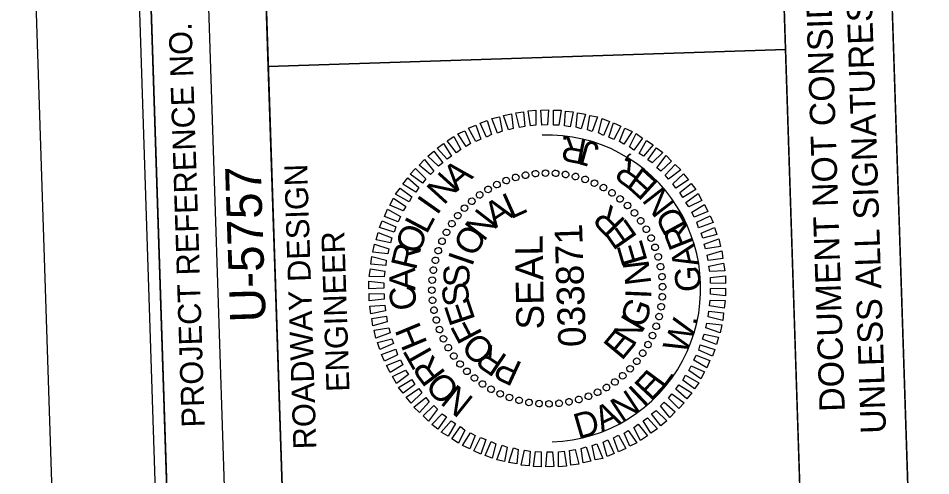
# Model space of a CAD drawing. Extents: x 1627314 to 1628469, y 762309 to 764247.
# Drawn here: x 1627314.2 to 1627512.6, y 763788.2 to 763887.6 of the extents above; entities that cross this region are included whole.
import ezdxf

# ---------------------------------------------------------------- set-up
doc = ezdxf.new("R2010")
doc.units = 0
for name, color, linetype in [('Old_Level_2', 7, 'Continuous'), ('Scratch_Level_0', 7, 'Continuous'), ('Sheet Data Field CELL', 7, 'Continuous'), ('Sheet Plot Border Inside CELL', 7, 'Continuous'), ('Sheet Plot Border Outside CELL', 7, 'Continuous'), ('Sheet Professional Seal CELL', 7, 'Continuous'), ('Sheet Profile CELL', 7, 'Continuous'), ('Sheet Profile Grid Major CELL', 7, 'Continuous'), ('Sheet Profile Grid Minor CELL', 7, 'Continuous'), ('Sheet Sticker Exception Certification CELL', 7, 'Continuous')]:
    doc.layers.add(name, color=color, linetype=linetype)

msp = doc.modelspace()

# ---------------------------------------------------------------- linework, layer by layer
at = {"layer": 'Old_Level_2'}
msp.add_lwpolyline([(1627507.79, 763781.61), (1627501.25, 763981.49), (1627565.16, 763983.58), (1627571.7, 763783.7)], close=True, dxfattribs=at)
at = {"layer": 'Scratch_Level_0'}
msp.add_arc((1627429.24, 763828.9), 33.36, 271.8735, 91.8735, dxfattribs=at)
at = {"layer": 'Sheet Plot Border Inside CELL'}
msp.add_lwpolyline([(1628446.34, 762357.53), (1628391.86, 764023.14), (1627337.33, 763988.65), (1627391.81, 762323.04)], close=True, dxfattribs=at)
at = {"layer": 'Sheet Plot Border Outside CELL'}
msp.add_lwpolyline([(1628469.21, 762345.27), (1628413.63, 764044.37), (1627314.22, 764008.4), (1627369.79, 762309.31)], close=True, dxfattribs=at)
at = {"layer": 'Sheet Professional Seal CELL'}
for p, q in [((1627420.27, 763852.37), (1627420.27, 763852.37)), ((1627422.35, 763853.03), (1627422.35, 763853.03)), ((1627424.53, 763853.51), (1627424.53, 763853.51)), ((1627426.67, 763853.88), (1627426.67, 763853.88)), ((1627428.87, 763854), (1627428.87, 763854)), ((1627431.07, 763853.92), (1627431.07, 763853.92)), ((1627433.23, 763853.64), (1627433.23, 763853.64)), ((1627435.35, 763853.26), (1627435.35, 763853.26)), ((1627437.47, 763852.63), (1627437.47, 763852.63)), ((1627416.38, 763850.44), (1627416.38, 763850.44)), ((1627418.3, 763851.5), (1627418.3, 763851.5)), ((1627439.5, 763851.79), (1627439.5, 763851.79)), ((1627441.48, 763850.86), (1627441.48, 763850.86)), ((1627414.52, 763849.23), (1627414.52, 763849.23)), ((1627443.32, 763849.67), (1627443.32, 763849.67)), ((1627445.11, 763848.38), (1627445.11, 763848.38)), ((1627411.21, 763846.37), (1627411.21, 763846.37)), ((1627412.81, 763847.92), (1627412.81, 763847.92)), ((1627446.71, 763846.93), (1627446.71, 763846.93)), ((1627409.76, 763844.77), (1627409.76, 763844.77)), ((1627448.26, 763845.33), (1627448.26, 763845.33)), ((1627408.47, 763842.98), (1627408.47, 763842.98)), ((1627449.57, 763843.62), (1627449.57, 763843.62)), ((1627407.28, 763841.14), (1627407.28, 763841.14)), ((1627450.78, 763841.76), (1627450.78, 763841.76)), ((1627406.34, 763839.15), (1627406.34, 763839.15)), ((1627451.84, 763839.84), (1627451.84, 763839.84)), ((1627405.51, 763837.13), (1627405.51, 763837.13)), ((1627452.71, 763837.87), (1627452.71, 763837.87)), ((1627404.88, 763835), (1627404.88, 763835)), ((1627453.38, 763835.79), (1627453.38, 763835.79)), ((1627404.5, 763832.89), (1627404.5, 763832.89)), ((1627453.85, 763833.6), (1627453.85, 763833.6)), ((1627404.22, 763830.73), (1627404.22, 763830.73)), ((1627454.22, 763831.46), (1627454.22, 763831.46)), ((1627404.14, 763828.53), (1627404.14, 763828.53)), ((1627429.24, 763828.9), (1627429.24, 763828.9)), ((1627454.34, 763829.27), (1627454.34, 763829.27)), ((1627454.26, 763827.06), (1627454.26, 763827.06)), ((1627404.26, 763826.33), (1627404.26, 763826.33)), ((1627453.98, 763824.9), (1627453.98, 763824.9)), ((1627404.63, 763824.19), (1627404.63, 763824.19)), ((1627453.6, 763822.79), (1627453.6, 763822.79)), ((1627405.1, 763822), (1627405.1, 763822)), ((1627452.97, 763820.67), (1627452.97, 763820.67)), ((1627405.77, 763819.92), (1627405.77, 763819.92)), ((1627452.14, 763818.64), (1627452.14, 763818.64)), ((1627406.64, 763817.95), (1627406.64, 763817.95)), ((1627451.2, 763816.66), (1627451.2, 763816.66)), ((1627407.7, 763816.04), (1627407.7, 763816.04)), ((1627450.01, 763814.82), (1627450.01, 763814.82)), ((1627408.91, 763814.17), (1627408.91, 763814.17)), ((1627448.72, 763813.03), (1627448.72, 763813.03)), ((1627410.22, 763812.47), (1627410.22, 763812.47)), ((1627411.77, 763810.87), (1627411.77, 763810.87)), ((1627447.27, 763811.43), (1627447.27, 763811.43)), ((1627413.37, 763809.42), (1627413.37, 763809.42)), ((1627443.96, 763808.57), (1627443.96, 763808.57)), ((1627445.67, 763809.87), (1627445.67, 763809.87)), ((1627415.16, 763808.13), (1627415.16, 763808.13)), ((1627417, 763806.94), (1627417, 763806.94)), ((1627442.1, 763807.36), (1627442.1, 763807.36)), ((1627418.98, 763806), (1627418.98, 763806)), ((1627421.01, 763805.17), (1627421.01, 763805.17)), ((1627436.13, 763804.76), (1627436.13, 763804.76)), ((1627438.21, 763805.43), (1627438.21, 763805.43)), ((1627440.19, 763806.29), (1627440.19, 763806.29)), ((1627423.13, 763804.53), (1627423.13, 763804.53)), ((1627425.25, 763804.15), (1627425.25, 763804.15)), ((1627427.41, 763803.87), (1627427.41, 763803.87)), ((1627429.61, 763803.8), (1627429.61, 763803.8)), ((1627431.81, 763803.92), (1627431.81, 763803.92)), ((1627433.95, 763804.29), (1627433.95, 763804.29))]:
    msp.add_line(p, q, dxfattribs=at)
for points in [[(1627418.43, 763862.66), (1627417.18, 763865.82), (1627418.82, 763866.18), (1627419.47, 763863.05)], [(1627420.81, 763863.34), (1627419.76, 763866.46), (1627421.45, 763866.81), (1627421.85, 763863.67)], [(1627423.19, 763863.87), (1627422.39, 763867.09), (1627424.08, 763867.3), (1627424.39, 763864.11)], [(1627425.58, 763864.25), (1627425.08, 763867.48), (1627426.77, 763867.64), (1627426.78, 763864.39)], [(1627428.08, 763864.38), (1627427.82, 763867.62), (1627429.52, 763867.68), (1627429.28, 763864.42)], [(1627430.58, 763864.41), (1627430.57, 763867.66), (1627432.23, 763867.62), (1627431.78, 763864.35)], [(1627432.99, 763864.24), (1627433.18, 763867.45), (1627434.89, 763867.3), (1627434.19, 763864.03)], [(1627435.55, 763863.92), (1627435.85, 763867.03), (1627437.56, 763866.74), (1627436.61, 763863.56)], [(1627437.97, 763863.35), (1627438.52, 763866.47), (1627440.18, 763866.17), (1627439.03, 763862.99)], [(1627413.74, 763860.81), (1627412.14, 763863.71), (1627413.72, 763864.41), (1627414.82, 763861.34)], [(1627416.06, 763861.78), (1627414.66, 763864.79), (1627416.19, 763865.39), (1627417.09, 763862.32)], [(1627440.39, 763862.68), (1627441.19, 763865.81), (1627442.76, 763865.21), (1627441.46, 763862.16)], [(1627442.62, 763861.75), (1627443.67, 763864.89), (1627445.25, 763864.19), (1627443.74, 763861.29)], [(1627411.62, 763859.74), (1627409.78, 763862.48), (1627411.31, 763863.18), (1627412.55, 763860.37)], [(1627444.95, 763860.83), (1627446.11, 763863.72), (1627447.68, 763863.02), (1627445.92, 763860.26)], [(1627447.14, 763859.7), (1627448.55, 763862.55), (1627449.98, 763861.59), (1627448.07, 763858.93)], [(1627407.46, 763857), (1627405.28, 763859.38), (1627406.7, 763860.38), (1627408.39, 763857.63)], [(1627409.47, 763858.37), (1627407.48, 763860.95), (1627408.95, 763861.95), (1627410.44, 763859.1)], [(1627449.19, 763858.26), (1627450.8, 763861.02), (1627452.28, 763860.12), (1627450.16, 763857.65)], [(1627405.56, 763855.44), (1627403.24, 763857.66), (1627404.55, 763858.76), (1627406.54, 763856.17)], [(1627451.14, 763856.83), (1627453, 763859.49), (1627454.34, 763858.43), (1627452.06, 763856.16)], [(1627403.82, 763853.63), (1627401.4, 763855.7), (1627402.56, 763856.94), (1627404.59, 763854.4)], [(1627453.1, 763855.14), (1627455.06, 763857.76), (1627456.25, 763856.54), (1627453.92, 763854.37)], [(1627402.13, 763851.77), (1627399.46, 763853.74), (1627400.62, 763854.98), (1627402.85, 763852.75)], [(1627454.9, 763853.55), (1627457.02, 763855.82), (1627458.26, 763854.66), (1627455.63, 763852.62)], [(1627400.64, 763849.82), (1627397.83, 763851.58), (1627398.89, 763852.92), (1627401.31, 763850.8)], [(1627456.51, 763851.6), (1627458.84, 763853.83), (1627459.93, 763852.51), (1627457.19, 763850.67)], [(1627399.21, 763847.73), (1627396.25, 763849.38), (1627397.26, 763850.71), (1627399.77, 763848.84)], [(1627458.07, 763849.75), (1627460.56, 763851.68), (1627461.55, 763850.41), (1627458.71, 763848.67)], [(1627397.92, 763845.73), (1627395.03, 763846.99), (1627395.83, 763848.52), (1627398.49, 763846.7)], [(1627459.4, 763847.59), (1627462.03, 763849.53), (1627462.88, 763848.01), (1627460.03, 763846.66)], [(1627460.66, 763845.48), (1627463.41, 763847.17), (1627464.16, 763845.65), (1627461.15, 763844.4)], [(1627396.85, 763843.4), (1627393.86, 763844.55), (1627394.51, 763846.12), (1627397.36, 763844.51)], [(1627461.79, 763843.32), (1627464.64, 763844.71), (1627465.29, 763843.23), (1627462.13, 763842.08)], [(1627395.97, 763841.12), (1627392.79, 763842.16), (1627393.34, 763843.58), (1627396.29, 763842.28)], [(1627395.15, 763838.84), (1627392.02, 763839.49), (1627392.47, 763841.05), (1627395.46, 763839.9)], [(1627462.67, 763840.9), (1627465.63, 763842.14), (1627466.13, 763840.61), (1627463.05, 763839.86)], [(1627394.58, 763836.42), (1627391.31, 763836.81), (1627391.66, 763838.52), (1627394.79, 763837.48)], [(1627463.39, 763838.52), (1627466.51, 763839.67), (1627466.91, 763837.98), (1627463.68, 763837.48)], [(1627464.02, 763836.14), (1627467.19, 763837.04), (1627467.4, 763835.4), (1627464.21, 763834.94)], [(1627394.11, 763833.85), (1627390.9, 763834.2), (1627391.09, 763835.85), (1627394.22, 763835.06)], [(1627464.4, 763833.75), (1627467.58, 763834.4), (1627467.84, 763832.71), (1627464.59, 763832.55)], [(1627393.79, 763831.44), (1627390.53, 763831.53), (1627390.78, 763833.19), (1627393.95, 763832.65)], [(1627393.72, 763828.94), (1627390.47, 763828.83), (1627390.47, 763830.48), (1627393.73, 763830.14)], [(1627464.73, 763831.26), (1627467.97, 763831.61), (1627467.98, 763829.96), (1627464.72, 763830.06)], [(1627464.76, 763828.86), (1627468.01, 763828.96), (1627468.01, 763827.31), (1627464.75, 763827.66)], [(1627393.75, 763826.54), (1627390.51, 763826.18), (1627390.5, 763827.83), (1627393.76, 763827.74)], [(1627394.08, 763824.04), (1627390.9, 763823.39), (1627390.64, 763825.08), (1627393.89, 763825.24)], [(1627464.69, 763826.35), (1627467.95, 763826.26), (1627467.7, 763824.6), (1627464.53, 763825.15)], [(1627394.46, 763821.66), (1627391.29, 763820.75), (1627391.08, 763822.4), (1627394.27, 763822.85)], [(1627464.37, 763823.94), (1627467.58, 763823.6), (1627467.39, 763821.94), (1627464.26, 763822.74)], [(1627463.9, 763821.38), (1627467.17, 763820.98), (1627466.83, 763819.27), (1627463.69, 763820.32)], [(1627395.09, 763819.28), (1627391.97, 763818.12), (1627391.57, 763819.81), (1627394.8, 763820.32)], [(1627463.33, 763818.96), (1627466.46, 763818.31), (1627466.01, 763816.74), (1627463.02, 763817.9)], [(1627395.81, 763816.9), (1627392.85, 763815.65), (1627392.35, 763817.18), (1627395.43, 763817.94)], [(1627462.51, 763816.68), (1627465.69, 763815.63), (1627465.14, 763814.21), (1627462.2, 763815.52)], [(1627396.69, 763814.48), (1627393.84, 763813.08), (1627393.19, 763814.56), (1627396.35, 763815.71)], [(1627397.82, 763812.31), (1627395.07, 763810.62), (1627394.32, 763812.15), (1627397.33, 763813.4)], [(1627461.63, 763814.4), (1627464.62, 763813.25), (1627463.97, 763811.67), (1627461.12, 763813.28)], [(1627399.09, 763810.2), (1627396.45, 763808.26), (1627395.6, 763809.79), (1627398.45, 763811.13)], [(1627460.56, 763812.06), (1627463.45, 763810.81), (1627462.65, 763809.28), (1627459.99, 763811.09)], [(1627400.41, 763808.04), (1627397.92, 763806.11), (1627396.93, 763807.38), (1627399.77, 763809.12)], [(1627459.27, 763810.07), (1627462.23, 763808.41), (1627461.22, 763807.08), (1627458.71, 763808.95)], [(1627401.97, 763806.19), (1627399.64, 763803.97), (1627398.55, 763805.28), (1627401.29, 763807.12)], [(1627457.84, 763807.97), (1627460.65, 763806.21), (1627459.59, 763804.88), (1627457.17, 763807)], [(1627403.58, 763804.24), (1627401.46, 763801.97), (1627400.22, 763803.13), (1627402.85, 763805.17)], [(1627456.35, 763806.02), (1627459.02, 763804.06), (1627457.86, 763802.82), (1627455.63, 763805.05)], [(1627405.39, 763802.65), (1627403.42, 763800.04), (1627402.23, 763801.25), (1627404.56, 763803.43)], [(1627454.66, 763804.16), (1627457.08, 763802.09), (1627455.92, 763800.85), (1627453.89, 763803.39)], [(1627407.34, 763800.97), (1627405.48, 763798.3), (1627404.14, 763799.36), (1627406.42, 763801.64)], [(1627451.02, 763800.79), (1627453.2, 763798.41), (1627451.78, 763797.42), (1627450.09, 763800.16)], [(1627452.92, 763802.36), (1627455.24, 763800.13), (1627453.93, 763799.04), (1627451.94, 763801.62)], [(1627409.29, 763799.53), (1627407.68, 763796.77), (1627406.2, 763797.68), (1627408.32, 763800.15)], [(1627411.34, 763798.1), (1627409.93, 763795.25), (1627408.5, 763796.2), (1627410.41, 763798.87)], [(1627449.01, 763799.43), (1627451, 763796.84), (1627449.53, 763795.84), (1627448.04, 763798.7)], [(1627413.53, 763796.97), (1627412.37, 763794.08), (1627410.8, 763794.78), (1627412.56, 763797.53)], [(1627444.74, 763796.99), (1627446.34, 763794.09), (1627444.76, 763793.39), (1627443.66, 763796.45)], [(1627446.86, 763798.06), (1627448.7, 763795.32), (1627447.17, 763794.61), (1627445.93, 763797.43)], [(1627415.86, 763796.04), (1627414.81, 763792.91), (1627413.24, 763793.6), (1627414.74, 763796.51)], [(1627418.09, 763795.11), (1627417.29, 763791.99), (1627415.72, 763792.59), (1627417.02, 763795.63)], [(1627420.51, 763794.44), (1627419.96, 763791.32), (1627418.3, 763791.62), (1627419.45, 763794.81)], [(1627440.05, 763795.13), (1627441.3, 763791.97), (1627439.66, 763791.62), (1627439.01, 763794.75)], [(1627442.42, 763796.01), (1627443.82, 763793), (1627442.29, 763792.4), (1627441.39, 763795.48)], [(1627422.93, 763793.87), (1627422.63, 763790.76), (1627420.92, 763791.05), (1627421.87, 763794.24)], [(1627425.49, 763793.56), (1627425.3, 763790.35), (1627423.59, 763790.49), (1627424.29, 763793.77)], [(1627427.9, 763793.38), (1627427.91, 763790.13), (1627426.25, 763790.18), (1627426.7, 763793.44)], [(1627430.4, 763793.42), (1627430.66, 763790.17), (1627428.96, 763790.12), (1627429.2, 763793.38)], [(1627432.9, 763793.55), (1627433.4, 763790.31), (1627431.71, 763790.16), (1627431.7, 763793.41)], [(1627435.29, 763793.93), (1627436.09, 763790.7), (1627434.4, 763790.5), (1627434.09, 763793.69)], [(1627437.67, 763794.45), (1627438.72, 763791.34), (1627437.03, 763790.98), (1627436.63, 763794.12)]]:
    msp.add_lwpolyline(points, close=True, dxfattribs=at)
for centre, major_axis in [((1627424.51, 763853.53), (-0.136, 0.707)), ((1627426.67, 763853.85), (-0.074, 0.716)), ((1627428.86, 763853.97), (-0.011, 0.72)), ((1627431.05, 763853.91), (0.052, 0.718)), ((1627433.22, 763853.66), (0.114, 0.711)), ((1627418.3, 763851.46), (-0.314, 0.648)), ((1627420.3, 763852.33), (-0.257, 0.673)), ((1627422.38, 763853.02), (-0.197, 0.693)), ((1627435.36, 763853.22), (0.176, 0.698)), ((1627437.46, 763852.59), (0.236, 0.68)), ((1627439.49, 763851.79), (0.294, 0.657)), ((1627416.37, 763850.42), (-0.369, 0.618)), ((1627441.45, 763850.81), (0.35, 0.629)), ((1627443.31, 763849.66), (0.404, 0.596)), ((1627412.83, 763847.86), (-0.471, 0.544)), ((1627414.54, 763849.22), (-0.422, 0.583)), ((1627445.07, 763848.35), (0.454, 0.559)), ((1627411.24, 763846.36), (-0.517, 0.501)), ((1627446.7, 763846.9), (0.501, 0.517)), ((1627409.78, 763844.72), (-0.559, 0.454)), ((1627448.2, 763845.31), (0.544, 0.471)), ((1627449.56, 763843.59), (0.583, 0.422)), ((1627408.48, 763842.97), (-0.596, 0.404)), ((1627450.77, 763841.77), (0.618, 0.369)), ((1627407.33, 763841.1), (-0.629, 0.35)), ((1627451.81, 763839.84), (0.648, 0.314)), ((1627406.35, 763839.15), (-0.657, 0.294)), ((1627452.67, 763837.83), (0.673, 0.257)), ((1627405.54, 763837.11), (-0.68, 0.236)), ((1627453.36, 763835.76), (0.693, 0.197)), ((1627404.92, 763835.02), (-0.698, 0.176)), ((1627453.87, 763833.63), (0.707, 0.136)), ((1627404.48, 763832.88), (-0.711, 0.114)), ((1627404.23, 763830.7), (-0.718, 0.052)), ((1627454.19, 763831.46), (0.716, 0.074)), ((1627404.16, 763828.51), (-0.72, -0.011)), ((1627454.32, 763829.28), (0.72, 0.011)), ((1627404.29, 763826.33), (-0.716, -0.074)), ((1627454.26, 763827.09), (0.718, -0.052)), ((1627404.61, 763824.17), (-0.707, -0.136)), ((1627454, 763824.92), (0.711, -0.114)), ((1627405.12, 763822.04), (-0.693, -0.197)), ((1627453.56, 763822.78), (0.698, -0.176)), ((1627405.81, 763819.96), (-0.673, -0.257)), ((1627452.94, 763820.68), (0.68, -0.236)), ((1627406.67, 763817.95), (-0.648, -0.314)), ((1627452.13, 763818.65), (0.657, -0.294)), ((1627407.71, 763816.03), (-0.618, -0.369)), ((1627451.15, 763816.69), (0.629, -0.35)), ((1627408.92, 763814.2), (-0.583, -0.422)), ((1627450, 763814.83), (0.596, -0.404)), ((1627410.28, 763812.48), (-0.544, -0.471)), ((1627448.7, 763813.07), (0.559, -0.454)), ((1627411.78, 763810.89), (-0.501, -0.517)), ((1627445.65, 763809.93), (0.471, -0.544)), ((1627447.24, 763811.44), (0.517, -0.501)), ((1627413.41, 763809.44), (-0.454, -0.559)), ((1627415.17, 763808.14), (-0.404, -0.596)), ((1627443.94, 763808.57), (0.422, -0.583)), ((1627417.03, 763806.99), (-0.35, -0.629)), ((1627418.99, 763806.01), (-0.294, -0.657)), ((1627440.18, 763806.33), (0.314, -0.648)), ((1627442.11, 763807.37), (0.369, -0.618)), ((1627421.02, 763805.2), (-0.236, -0.68)), ((1627423.12, 763804.58), (-0.176, -0.698)), ((1627425.26, 763804.13), (-0.114, -0.711)), ((1627427.44, 763803.88), (-0.052, -0.718)), ((1627431.81, 763803.95), (0.074, -0.716)), ((1627433.97, 763804.27), (0.136, -0.707)), ((1627436.1, 763804.77), (0.197, -0.693)), ((1627438.18, 763805.46), (0.257, -0.673)), ((1627429.62, 763803.82), (0.011, -0.72))]:
    msp.add_ellipse(centre, major_axis=major_axis, ratio=0.999708, dxfattribs=at)
at = {"layer": 'Sheet Profile CELL'}
for p, q in [((1627359.37, 763776.71), (1627352.83, 763976.65)), ((1627368.59, 763877.11), (1627480.98, 763880.79))]:
    msp.add_line(p, q, dxfattribs=at)
for points in [[(1627340.28, 763976.24), (1627389.32, 762477.04), (1628438.76, 762511.37), (1628389.72, 764010.57)], [(1627368.59, 763877.11), (1627365.32, 763977.06), (1627477.76, 763980.74), (1627481.03, 763880.79)], [(1627346.82, 763776.3), (1627340.28, 763976.24), (1627365.32, 763977.06), (1627371.86, 763777.12)], [(1627371.86, 763777.12), (1627368.59, 763877.11), (1627481.03, 763880.79), (1627484.3, 763780.79)]]:
    msp.add_lwpolyline(points, close=True, dxfattribs=at)
at = {"layer": 'Sheet Profile Grid Major CELL'}
msp.add_lwpolyline([(1627363.17, 763276.61), (1627361.53, 763326.59), (1627861.27, 763342.93), (1627859.63, 763392.91), (1627359.9, 763376.56), (1627358.26, 763426.53), (1627858, 763442.88), (1627856.36, 763492.85), (1627356.63, 763476.51), (1627354.99, 763526.48), (1627854.73, 763542.83), (1627853.09, 763592.8), (1627353.36, 763576.45), (1627351.73, 763626.43), (1627851.46, 763642.77), (1627849.82, 763692.75), (1627350.09, 763676.4), (1627348.46, 763726.37), (1627848.19, 763742.72), (1627846.55, 763792.69), (1627346.82, 763776.35), (1627345.96, 763802.63)], dxfattribs=at)
at = {"layer": 'Sheet Sticker Exception Certification CELL'}
for p, q in [((1627501.25, 763981.49), (1627507.79, 763781.56)), ((1627501.25, 763981.49), (1627507.79, 763781.56)), ((1627484.3, 763780.79), (1627477.76, 763980.72)), ((1627484.3, 763780.79), (1627477.76, 763980.72))]:
    msp.add_line(p, q, dxfattribs=at)

# ---------------------------------------------------------------- texts
at = {"layer": 'Sheet Data Field CELL'}
msp.add_text('U-5757', height=7.75, rotation=91.8735, dxfattribs=at).set_placement((1627368.04, 763821.64))
at = {"layer": 'Sheet Professional Seal CELL'}
for s, height, rotation, p in [('A', 5.64, 40.4906, (1627409.59, 763849.87)), ('N', 5.64, 47.6924, (1627406.74, 763846.82)), ('I', 5.64, 54.8936, (1627405.26, 763844.62)), ('L', 5.64, 24.2743, (1627421.3, 763843.9)), ('A', 5.64, 33.6337, (1627417.91, 763841.83)), ('R', 5.64, 134.3549, (1627446.52, 763843.57)), ('L', 5.64, 62.0943, (1627403, 763840.5)), ('N', 5.64, 52.3501, (1627415.41, 763838.9)), ('O', 5.64, 69.2946, (1627401.29, 763836.04)), ('E', 5.64, 124.9976, (1627448.98, 763840.1)), ('O', 5.64, 61.707, (1627413.52, 763835.49)), ('R', 5.64, 76.4946, (1627400.65, 763832.66)), ('SEAL', 5.998, 90.8735, (1627428.53, 763820.02)), ('E', 5.64, 106.2852, (1627451.11, 763834.87)), ('I', 5.64, 71.0631, (1627412.88, 763833.46)), ('N', 5.64, 96.9299, (1627451.87, 763829.94)), ('A', 5.64, 90.8938, (1627400.59, 763828.46)), ('S', 5.64, 89.7739, (1627412.32, 763829.14)), ('C', 5.64, 98.0933, (1627401.02, 763824.52)), ('S', 5.64, 99.1291, (1627412.49, 763825.55)), ('E', 5.64, 108.4845, (1627413.65, 763822.13)), ('I', 5.64, 87.5747, (1627451.83, 763826.58)), ('G', 5.64, 68.8637, (1627450.14, 763819.98)), ('N', 5.64, 59.5074, (1627448.02, 763816.1)), ('H', 5.64, 112.4929, (1627403.27, 763816.99)), ('F', 5.64, 117.8405, (1627415.26, 763818.98)), ('O', 5.64, 136.5547, (1627418.31, 763815.78)), ('E', 5.64, 50.1504, (1627445.42, 763813.02)), ('R', 5.64, 145.9131, (1627420.82, 763814.11)), ('T', 5.64, 119.6932, (1627405.02, 763813.8)), ('R', 5.64, 126.894, (1627407.33, 763810.47)), ('P', 5.64, 155.2724, (1627424.07, 763812.62)), ('O', 5.64, 134.0952, (1627410.54, 763807.12)), ('N', 5.64, 141.297, (1627413.52, 763804.92))]:
    msp.add_text(s, height=height, rotation=rotation, dxfattribs=at).set_placement(p)
at = {"layer": 'Sheet Profile CELL'}
for s, height, p in [('PROJECT REFERENCE NO.', 5.0001, (1627354.78, 763798.78)), ('ROADWAY DESIGN', 5.0001, (1627379.05, 763794.02)), ('ENGINEER', 5, (1627386.24, 763806.51))]:
    msp.add_text(s, height=height, rotation=91.8735, dxfattribs=at).set_placement(p)
at = {"layer": 'Sheet Profile Grid Minor CELL'}
for s, height, rotation, p in [('R', 5.5, 169.2275, (1627438.09, 763861.18)), ('.', 5.5, 176.154, (1627434.13, 763862.01)), ('J', 5.5, 164.359, (1627440.8, 763860.31)), (',', 5.5, 151.1787, (1627447.66, 763856.84)), ('R', 5.5, 144.2523, (1627450.89, 763854.42)), ('E', 5.5, 137.6693, (1627453.68, 763851.77)), ('N', 5.5, 127.7376, (1627457.25, 763847.21)), ('D', 5.5, 118.5929, (1627459.81, 763842.53)), ('033871', 5.998, 91.8735, (1627437.67, 763816.27)), ('R', 5.5, 111.6665, (1627461.23, 763838.74)), ('A', 5.5, 103.4807, (1627462.31, 763834.09)), ('G', 5.5, 93.549, (1627462.7, 763828.3)), ('W', 5.5, 68.7626, (1627459.37, 763814.33)), ('.', 5.5, 80.3687, (1627461.69, 763820.69)), ('E', 5.5, 46.9243, (1627451.79, 763804.17)), ('L', 5.5, 53.5073, (1627454.48, 763806.91)), ('N', 5.5, 33.4721, (1627445.42, 763799.6)), ('I', 5.5, 43.4038, (1627450.23, 763802.83)), ('A', 5.5, 25.2863, (1627441.08, 763797.59)), ('D', 5.5, 16.1417, (1627435.96, 763796.11))]:
    msp.add_text(s, height=height, rotation=rotation, dxfattribs=at).set_placement(p)
at = {"layer": 'Sheet Sticker Exception Certification CELL'}
for s, p in [('UNLESS ALL SIGNATURES COMPLETED', (1627502.91, 763797.41)), ('UNLESS ALL SIGNATURES COMPLETED', (1627502.91, 763797.41)), ('DOCUMENT NOT CONSIDERED FINAL', (1627493.95, 763802.19)), ('DOCUMENT NOT CONSIDERED FINAL', (1627493.95, 763802.19))]:
    msp.add_text(s, height=5.5, rotation=91.8735, dxfattribs=at).set_placement(p)

doc.saveas('drawing.dxf')
